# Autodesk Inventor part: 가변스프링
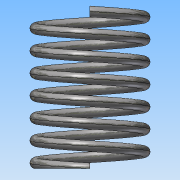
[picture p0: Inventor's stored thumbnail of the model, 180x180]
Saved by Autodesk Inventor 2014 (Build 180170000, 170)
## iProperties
Created: 2020-01
Part Number: 가변스프링
Material: 스테인레스 스틸
Document SubType Name: Modeling
Designer: net
Density: 8.08 g/cm^3
Appearance: 반연마
Mass: 11.074 g
Surface Area: 27.6471 cm^2
Volume: 1.37054 cm^3
Author: net
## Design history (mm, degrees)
sketch "스케치1"
  geometry: L1 (0, 0)-(10, 0); L2 (10, 0)-(10, 28.7); L3 (10, 28.7)-(0, 28.7); L4 (0, 28.7)-(0, 0); C1 r 1 at (10, 0)
  constraints: 8 end point, 2 parallel, 1 centre point, 1 coincident, 1 horizontal, 1 perpendicular
  dimensions: "d0" = 20 diameter of L2 L4; "d1" = 28.7 distance of L1.end L2.end (derived); "d2" = 2 diameter of C1
feature "코일1" sketch "스케치1" pitch "d3" = 10; turns "d5" = 7; dims "d4" = 28.7 (= d1), "d6" = 0, angle "d7" = 90 deg, angle "d8" = 90 deg, "d9" = 0, "d10" = 0
sketch "스케치2"
  geometry: C1 r 11.5 at (0, 0); 1 further point
  constraints: 1 centre point, 1 coincident
  dimensions: "d11" = 23 diameter of C1
extrude "돌출1" cut sketch "스케치2" distance "d12" = 10; taper "d13" = 0 deg
node "작업 평면1"
sketch "스케치3"
  geometry: C1 r 12 at (0, 0); 1 further point
  constraints: 1 centre point, 1 coincident
  dimensions: "d15" = 24 diameter of C1
extrude "돌출2" cut sketch "스케치3" distance "d16" = 10; taper "d17" = 0 deg
node "솔리드1"
other parameters: "d14" = 42
